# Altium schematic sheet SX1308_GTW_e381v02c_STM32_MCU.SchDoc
size B; DrawnBy: Erik Fountain; DocumentNumber: 3; SheetNumber: 3; SheetTotal: 5; PageSetup: Record=PageOptions|CenterHorizontal=True|CenterVertical=True|PrintScale=0.72|XCorrection=1.00|YCorrection=1.00|PrintKind=0|BorderSize=5000000|LeftOffset=0|BottomOffset=0|Orientation=2|PaperLength=1000|PaperWidth=1000|Scale=100|PaperSource=7|PrintQuality=-4|MediaType=1|DitherType=10|PaperKind=Letter|PrintScaleMode=1
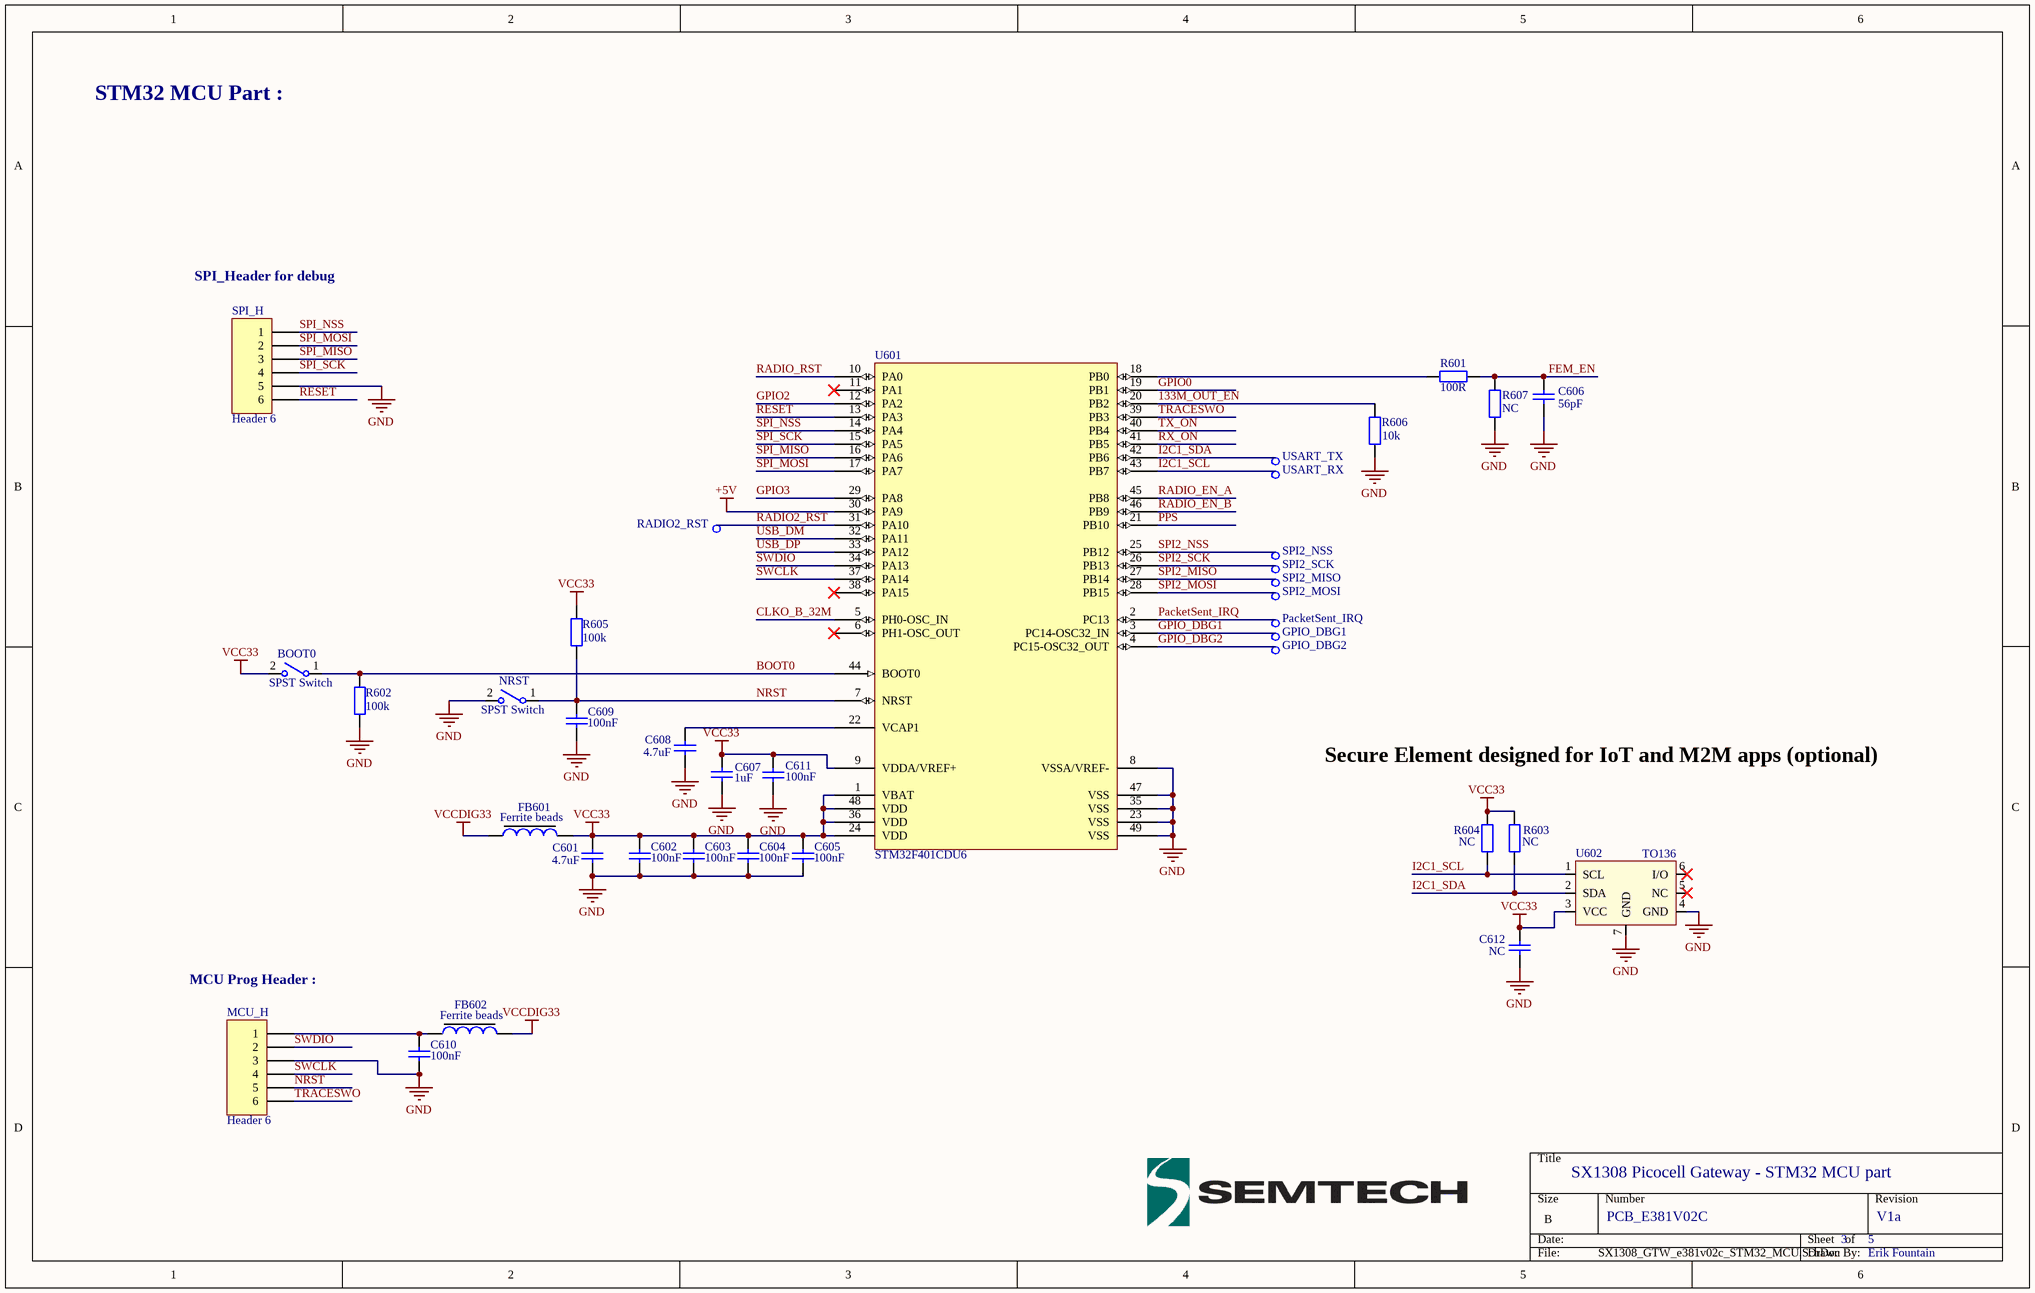
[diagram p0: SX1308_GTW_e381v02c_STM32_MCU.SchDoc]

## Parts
BOOT0  SPST Switch  [KXT_series_switch_3.5x2.0mm]
C601  value 4.7uF  [rlc_603_smd]  (hidden comment: Cap)
C602  value 100nF  [rlc_402_smd]  (hidden comment: Cap)
C603  value 100nF  [rlc_402_smd]  (hidden comment: Cap)
C604  value 100nF  [rlc_402_smd]  (hidden comment: Cap)
C605  value 100nF  [rlc_402_smd]  (hidden comment: Cap)
C606  value 56pF  [rlc_402_smd]  (hidden comment: Cap)
C607  value 1uF  [rlc_402_smd]  (hidden comment: Cap)
C608  value 4.7uF  [rlc_603_smd]  (hidden comment: Cap)
C609  value 100nF  [rlc_402_smd]  (hidden comment: Cap)
C610  value 100nF  [rlc_402_smd]  (hidden comment: Cap)
C611  value 100nF  [rlc_402_smd]  (hidden comment: Cap)
C612  value NC  [rlc_402_smd]  (hidden comment: Cap)
FB601  Ferrite beads  [rlc_402_smd]
FB602  Ferrite beads  [rlc_402_smd]
GPIO_DBG1  Test Pin  [PIN_SMD]  (value not drawn)
GPIO_DBG2  Test Pin  [PIN_SMD]  (value not drawn)
MCU_H  Header 6  [HDR1X6_SMD]
NRST  SPST Switch  [KXT_series_switch_3.5x2.0mm]
PacketSent_IRQ  Test Pin  [PIN_SMD]  (value not drawn)
R601  value 100R  [rlc_402_smd]  (hidden comment: Resistor)
R602  value 100k  [rlc_402_smd]  (hidden comment: Resistor)
R603  value NC  [rlc_201_smd]  (hidden comment: Resistor)
R604  value NC  [rlc_201_smd]  (hidden comment: Resistor)
R605  value 100k  [rlc_402_smd]  (hidden comment: Resistor)
R606  value 10k  [rlc_402_smd]  (hidden comment: Resistor)
R607  value NC  [rlc_402_smd]  (hidden comment: Resistor)
RADIO2_RST  Test Pin  [PIN_SMD]  (value not drawn)
SPI2_MISO  Test Pin  [PIN_SMD]  (value not drawn)
SPI2_MOSI  Test Pin  [PIN_SMD]  (value not drawn)
SPI2_NSS  Test Pin  [PIN_SMD]  (value not drawn)
SPI2_SCK  Test Pin  [PIN_SMD]  (value not drawn)
SPI_H  Header 6  [HDR1X6_SMD]
U601  STM32F401CDU6  [UFQFPN48_7x7MM]
U602  TO136  [DFN6_3X3mm]
USART_RX  Test Pin  [PIN_SMD]  (value not drawn)
USART_TX  Test Pin  [PIN_SMD]  (value not drawn)

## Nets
+5V: U601.30(PA9)
GND: C601.1 C602.1 C603.1 C604.1 C605.1 C606.1 C607.1 C608.1 C609.1 C610.1 C611.1 C612.1 MCU_H.3 NRST.2(NO) R602.1 R606.1 R607.1 SPI_H.5 U601.8(VSSA/VREF-) U601.23(VSS) U601.35(VSS) U601.47(VSS) U601.49(VSS) U602.4(GND) U602.7(GND)
VCC33: BOOT0.2(NO) C601.2 C602.2 C603.2 C604.2 C605.2 C607.2 C611.2 C612.2 FB601.2 R603.2 R604.2 R605.2 U601.1(VBAT) U601.9(VDDA/VREF+) U601.24(VDD) U601.36(VDD) U601.48(VDD) U602.3(VCC)
VCCDIG33: FB601.1 FB602.2
133M_OUT_EN: R606.2 U601.20(PB2)
BOOT0: BOOT0.1(COMMON) R602.2 U601.44(BOOT0)
CLKO_B_32M: U601.5(PH0-OSC_IN)
FEM_EN: C606.2 R601.2 R607.2
GPIO0: U601.19(PB1)
GPIO2: U601.12(PA2)
GPIO3: U601.29(PA8)
GPIO_DBG1: GPIO_DBG1.1(pin) U601.3(PC14-OSC32_IN)
GPIO_DBG2: GPIO_DBG2.1(pin) U601.4(PC15-OSC32_OUT)
I2C1_SCL: R604.1 U601.43(PB7) U602.1(SCL) USART_RX.1(pin)
I2C1_SDA: R603.1 U601.42(PB6) U602.2(SDA) USART_TX.1(pin)
NRST: C609.2 MCU_H.5 NRST.1(COMMON) R605.1 U601.7(NRST)
PacketSent_IRQ: PacketSent_IRQ.1(pin) U601.2(PC13)
PPS: U601.21(PB10)
RADIO2_RST: RADIO2_RST.1(pin) U601.31(PA10)
RADIO_EN_A: U601.45(PB8)
RADIO_EN_B: U601.46(PB9)
RADIO_RST: U601.10(PA0)
RESET: SPI_H.6 U601.13(PA3)
RX_ON: U601.41(PB5)
SPI2_MISO: SPI2_MISO.1(pin) U601.27(PB14)
SPI2_MOSI: SPI2_MOSI.1(pin) U601.28(PB15)
SPI2_NSS: SPI2_NSS.1(pin) U601.25(PB12)
SPI2_SCK: SPI2_SCK.1(pin) U601.26(PB13)
SPI_MISO: SPI_H.3 U601.16(PA6)
SPI_MOSI: SPI_H.2 U601.17(PA7)
SPI_NSS: SPI_H.1 U601.14(PA4)
SPI_SCK: SPI_H.4 U601.15(PA5)
SWCLK: MCU_H.4 U601.37(PA14)
SWDIO: MCU_H.2 U601.34(PA13)
TRACESWO: MCU_H.6 U601.39(PB3)
TX_ON: U601.40(PB4)
USB_DM: U601.32(PA11)
USB_DP: U601.33(PA12)
NetC608_2: C608.2 U601.22(VCAP1)
NetC610_2: C610.2 FB602.1 MCU_H.1
NetR601_1: R601.1 U601.18(PB0)

Not connected (* = marked no-connect by the designer): U601 6(PH1-OSC_OUT)* 11(PA1)* 38(PA15)*; U602 5(NC)* 6(I/O)*

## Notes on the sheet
- STM32 MCU Part :
- (near SPI_H) SPI_Header for debug
- Secure Element designed for IoT and M2M apps (optional)
- (near MCU_H) MCU Prog Header :
- SX1308 Picocell Gateway - STM32 MCU part
- PCB_E381V02C
- V1a

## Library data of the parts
BOOT0 NRST = SW-SPST: SPST, N.O. - Tactile Switch; Value: KXT121LHS
C601-C612 = Cap: Capacitor SMD
FB601 FB602 = Ferrite beads: Value: VAL?
GPIO_DBG1 GPIO_DBG2 PacketSent_IRQ RADIO2_RST SPI2_MISO SPI2_MOSI SPI2_NSS SPI2_SCK USART_RX USART_TX = test_pin
MCU_H SPI_H = Header 6: Header, 6-Pin
R601-R607 = Resistor: Resistor SMD - IEC symbol version
U601 = STM32F401CDU6: STM32 ARM Cortex M4 32-bit MCU with 256Kbytes Flash/96kB RAM, UFQFPN48 package
U602 = TO136: TO136 - Secure Element designed for IoT and M2M applications.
